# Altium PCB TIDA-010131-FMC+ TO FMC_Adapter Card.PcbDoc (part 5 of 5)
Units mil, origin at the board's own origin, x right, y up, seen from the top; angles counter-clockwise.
Board outline 2874.02 x 2362.2 mil, 12 copper layers (L1_Top Layer, L2_GND, L3_GND, L4_Signal layer1, L5_GND, L6_Signal Layer2, L7_GND, L8_Signal Layer3, L9_GND, L10_Signal Layer4, L11_GND, L12_Bottom Layer), stack 65.6 mil thick; 64 components, 219 nets, 2252 pads, 791 vias.
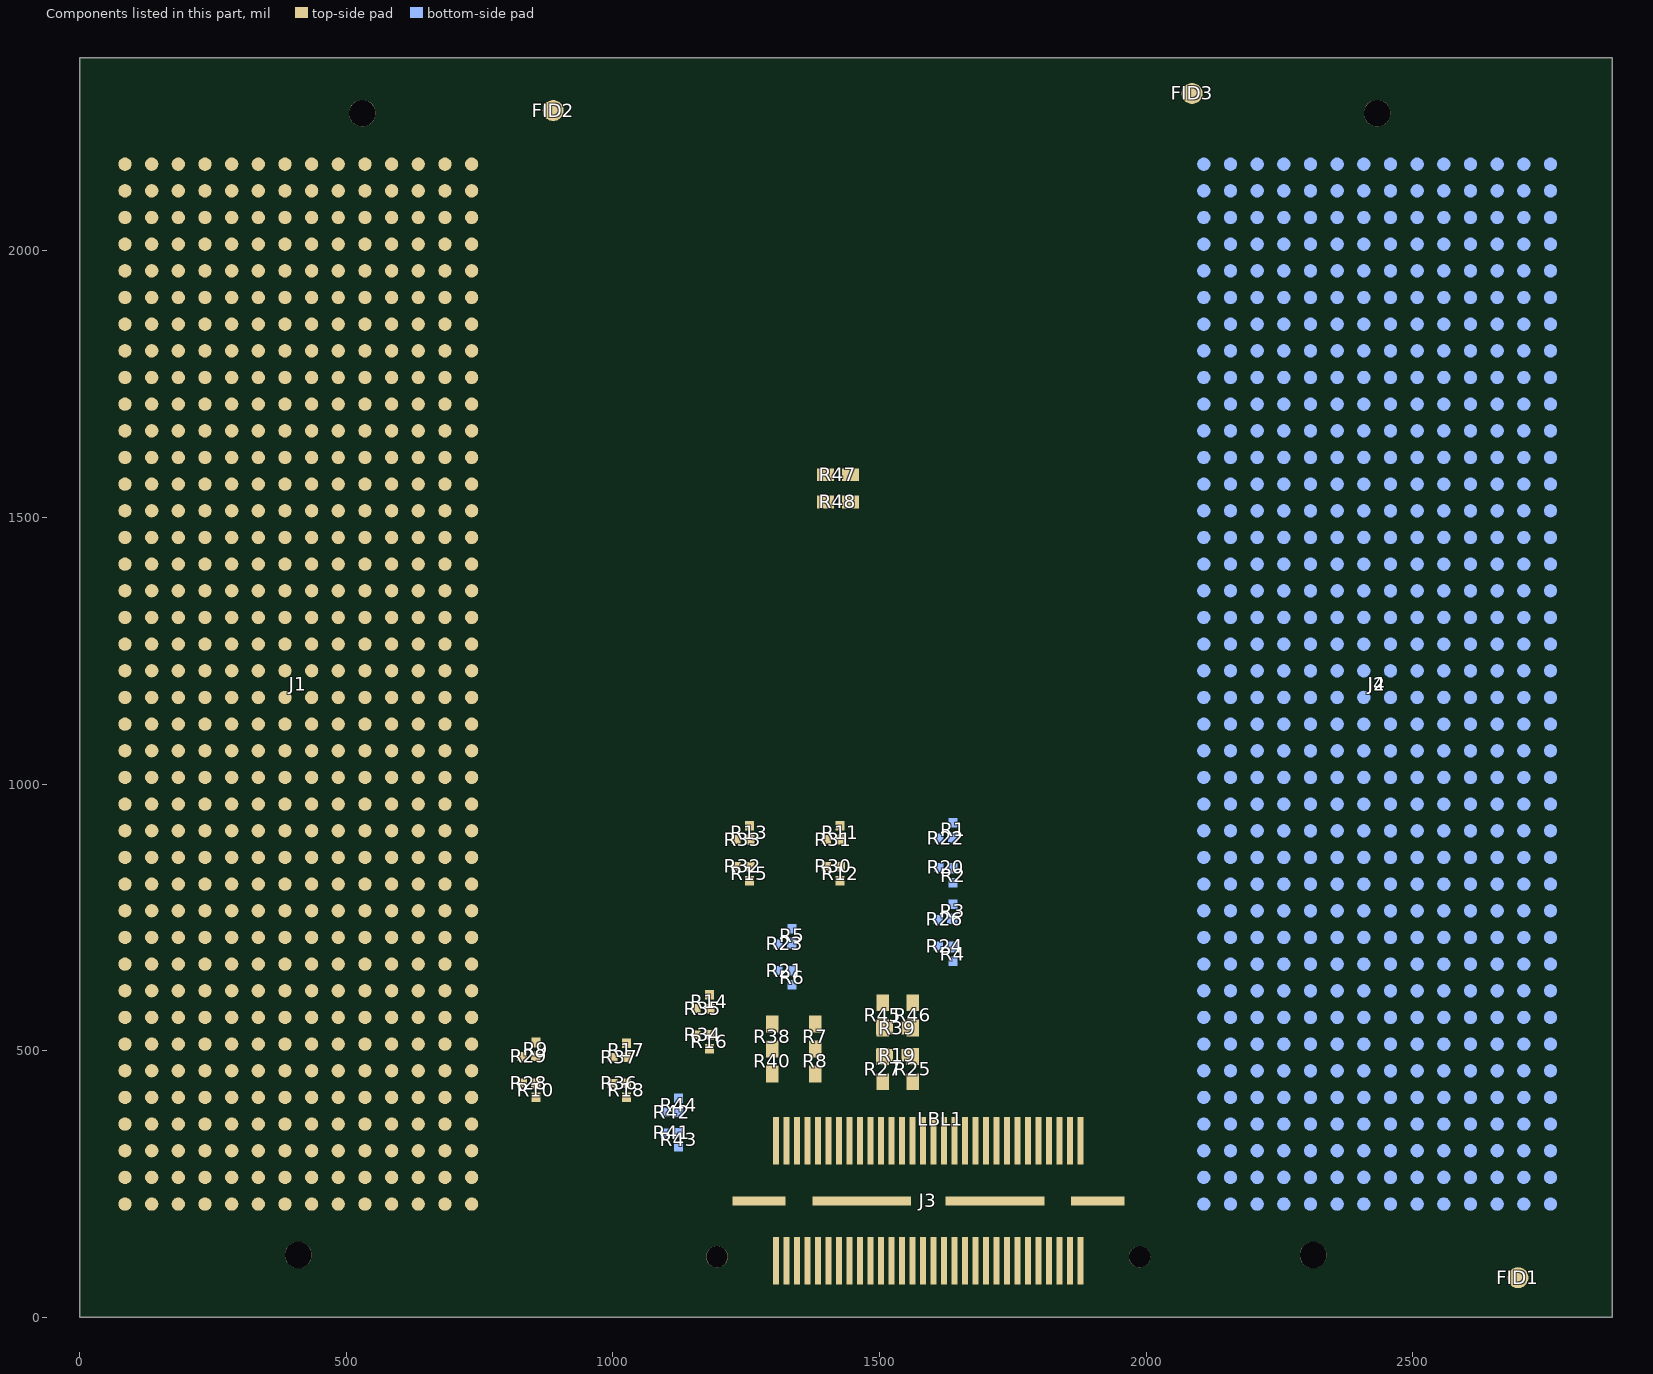
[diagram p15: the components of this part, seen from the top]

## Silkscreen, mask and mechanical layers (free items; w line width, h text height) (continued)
Drill Drawing:
  circle w10: c877.72,4292.33 r33.33
  lines w10: 844.39,3959 877.72,3975.67 911.06,3959 894.39,3992.33 911.06,4025.67 877.72,4009 844.39,4025.67 861.06,3992.33 844.39,3959 ; 844.39,4109 911.06,4109 911.06,4175.67 844.39,4175.67 844.39,4109
  lines w15: 784.6,3914 4309.68,3914 ; 784.6,4364 4309.68,4364 ; 1335.48,3764 1335.48,4514 ; 1935.32,3764 1935.32,4514 ; 3025,3764 3025,4514 ; 3530.88,3764 3530.88,4514 ; 784.6,3764 4309.68,3764 4309.68,4514 784.6,4514 784.6,3764
  text "Symbol" at 874.6,4409 h72
  text "Count" at 1380.48,4409 h72
  text "Hole Size" at 1980.32,4409 h72
  text "Plated" at 3070,4409 h72
  text "Hole Type" at 3575.88,4409 h72
  text "2" at 1380.48,4259 h60
  text "40.16mil (1.020mm)" at 1980.32,4259 h60
  text "NPTH" at 3070,4259 h60
  text "Round" at 3575.88,4259 h60
  text "6" at 1380.48,4109 h60
  text "50.00mil (1.270mm)" at 1980.32,4109 h60
  text "NPTH" at 3070,4109 h60
  text "Round" at 3575.88,4109 h60
  text "791" at 1380.48,3959 h60
  text "8.00mil (0.203mm)" at 1980.32,3959 h60
  text "PTH" at 3070,3959 h60
  text "Round" at 3575.88,3959 h60
  text "799 Total" at 1380.48,3809 h60
  text "FOR 8MIL DRILL +0/-8MIL" at 1924.29,3511.6 h60
  text "FOR NPTH DRILL +/-2MIL" at 1922,3390 h60
  text "DRILL DRAWING" at -4846.13,-1935.49 h60

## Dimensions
0,2362.2 to 0,0 on M2 Board Dimensions
0,0 to 2874.02,0 on M2 Board Dimensions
